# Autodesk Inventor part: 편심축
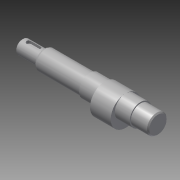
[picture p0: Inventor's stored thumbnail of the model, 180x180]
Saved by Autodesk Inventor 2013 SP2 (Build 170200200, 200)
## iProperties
Created: 2017-08
Part Number: 편심축
Material: 강철, 연강
Document SubType Name: Modeling
Designer: mduedu
Density: 1 g/cm^3
Author: mduedu
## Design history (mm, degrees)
sketch "스케치1"
  geometry: L1 (0, 0)-(118, 0); L2 (118, 0)-(118, 8.5); L3 (118, 8.5)-(103, 8.5); L4 (103, 8.5)-(103, 9.5); L5 (103, 9.5)-(59, 9.5); L6 (59, 9.5)-(59, 8.5); L7 (59, 8.5)-(19, 8.5); L8 (19, 8.5)-(19, 6); L9 (19, 6)-(0, 6); L10 (0, 6)-(0, 0)
  constraints: 20 end point, 6 parallel, 2 collinear, 2 perpendicular, 1 horizontal
  dimensions: "d0" = 118 distance of L1.start L1.end; "d1" = 17 diameter of L3 L1; "d2" = 19 diameter of L5 L1; "d3" = 12 diameter of L9 L1; "d4" = 19 distance of L8.end L9.end; "d5" = 15 distance of L2.end L3.end; "d6" = 44 distance of L4.end L5.end
revolve "회전1" sketch "스케치1" stored, may be unused: angle "d7" = 90 deg
node "작업 평면1"
sketch "스케치2"
  geometry: C1 r 9.5 at (0, 0) reference; C2 r 13 at (0, -3.5); 1 further point
  constraints: 1 centre point, 1 tangent, 1 vertical alignment
  dimensions: "d8" = 3.5 distance of point (0, 0) C2.centre
extrude "돌출1" join sketch "스케치2" stored distance "d9" = 18; taper "d10" = 0 deg
chamfer "모따기1" distance "d11" = 1; stored, may be unused: second distance "d12" = 2, angle "d13" = 45 deg
node "작업 평면2"
sketch "스케치3"
  geometry: L1 (3.5, -2)-(-4.5, -2); L2 (-4.5, -2)-(-4.5, 2); L3 (-4.5, 2)-(3.5, 2); L4 (3.5, 2)-(3.5, -2); L5 (9.5, 6)-(9.5, -6) reference; A1 r 2 centre (3.5, 0) between (3.5, -2) and (3.5, 2); A2 r 2 centre (-4.5, 0) between (-4.5, 2) and (-4.5, -2); A3 r 2 centre (3.5, 0) between (3.5, 2) and (3.5, -2); A4 r 2 centre (-4.5, 0) between (-4.5, -2) and (-4.5, 2); 1 further point
  constraints: 8 end point, 8 point on circle, 4 centre point, 2 midpoint, 2 parallel, 1 horizontal, 1 horizontal alignment, 1 perpendicular
  dimensions: "d14" = 12 dimension on A2 A1; "d16" = 4 distance between parallel lines of L3 L1; "d17" = 4 distance edge to line of A1 L5
extrude "돌출2" cut sketch "스케치3" distance "d18" = 2.5; taper "d19" = 0 deg
chamfer "모따기2" distance "d20" = 1; stored, may be unused: second distance "d21" = 2, angle "d22" = 45 deg
chamfer "모따기3" distance "d23" = 1; stored, may be unused: second distance "d24" = 2, angle "d25" = 60 deg
fillet "모깎기1" dims "d26" = 0.5
hole "구멍1" diameter "d29" = 3.242; stored, may be unused: countersink angle "d33" = 90 deg, drill point angle "d35" = 118 deg; dims "d30" = 8, "d31" = 4, "d32" = 2, "d34" = 10, "d36" = 10, "d37" = 10
node "솔리드1"
node "절단 모서리 투영1"
